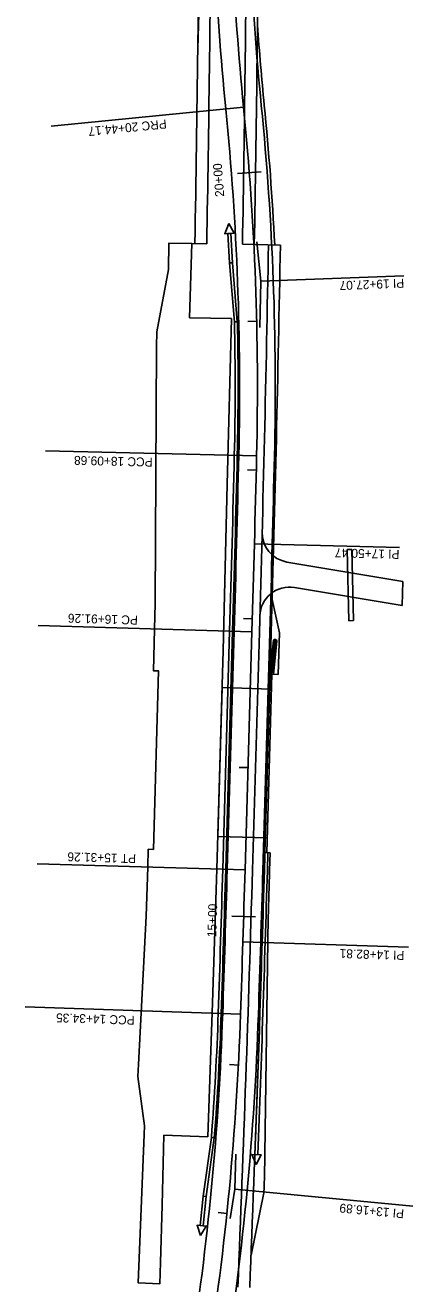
# Model space of a CAD drawing. Extents: x 1445610 to 1446352, y 2042797 to 2056486.
# Drawn here: x 1445983 to 1446244, y 2043758 to 2044604 of the extents above; entities that cross this region are included whole.
import ezdxf

# ---------------------------------------------------------------- set-up
doc = ezdxf.new("R2010")
doc.units = 0
for name, color, linetype in [('20', 7, 'Continuous'), ('Default', 7, 'Continuous'), ('Level 43', 7, 'Continuous'), ('MOT_Barrier Wall', 7, 'Continuous'), ('MOT_TIAB', 7, 'Continuous'), ('R_Bridge', 7, 'Continuous'), ('R_Horz Alg', 7, 'Continuous'), ('R_Horz Alg Annot', 7, 'Continuous'), ('R_Horz Alg Stationing', 7, 'Continuous'), ('R_Impact Attenuator', 7, 'Continuous'), ('R_Proposed Road', 7, 'Continuous'), ('R_Shld', 7, 'Continuous')]:
    doc.layers.add(name, color=color, linetype=linetype)

msp = doc.modelspace()

# ---------------------------------------------------------------- linework, layer by layer
at = {"layer": '20'}
for points in [[(1446099.19, 2044587.77), (1446099.81, 2044645.31), (1446100.22, 2044692.73), (1446100.65, 2044743.22), (1446101.46, 2044815.39), (1446102.41, 2044882.46), (1446103.41, 2044940.88), (1446106.1, 2045068.66), (1446107.43, 2045122.08), (1446109.28, 2045188.98), (1446109.28, 2045188.98), (1446109.52, 2045197.16), (1446117.13, 2045296.98), (1446119.67, 2045296.9), (1446109.26, 2044914.17), (1446105.78, 2044809.37), (1446102.6, 2044702.27), (1446099.67, 2044603.66)], [(1446106.06, 2043856.72), (1446076.44, 2043857.82), (1446075.37, 2043810.87), (1446074.2, 2043772.3), (1446073.76, 2043757.95), (1446059.18, 2043758.55), (1446063.09, 2043858.31), (1446063.3, 2043864.15), (1446058.99, 2043897.27), (1446059.27, 2043905.25), (1446064.53, 2044004.95), (1446065.52, 2044038.02), (1446065.87, 2044050.02), (1446069.37, 2044049.92), (1446072.86, 2044169.87), (1446069.36, 2044169.97), (1446070.17, 2044197.96), (1446070.66, 2044215.07), (1446071.41, 2044387.78), (1446071.61, 2044397.76), (1446079.43, 2044439.54), (1446079.75, 2044457.36), (1446095.2, 2044457.08), (1446093.66, 2044407.15), (1446121.8, 2044406.59), (1446119.04, 2044295.1), (1446116.28, 2044183.61), (1446112, 2044036.67), (1446109.03, 2043946.7)]]:
    msp.add_lwpolyline(points, close=True, dxfattribs=at)
at = {"layer": 'Default'}
msp.add_line((1446112.64, 2044058.66), (1446115.55, 2044158.62), dxfattribs=at)
at = {"layer": 'Level 43'}
for p, q in [((1446199.73, 2044251.32), (1446202.73, 2044251.39)), ((1446200.89, 2044203.54), (1446199.73, 2044251.32)), ((1446203.89, 2044203.61), (1446202.73, 2044251.39)), ((1446200.89, 2044203.54), (1446203.89, 2044203.61))]:
    msp.add_line(p, q, dxfattribs=at)
at = {"layer": 'MOT_Barrier Wall'}
for p, q in [((1446119.49, 2044463.76), (1446121.49, 2044463.87)), ((1446120.47, 2044443.95), (1446119.49, 2044463.77)), ((1446122.47, 2044444.05), (1446121.49, 2044463.87)), ((1446122.47, 2044444.05), (1446120.47, 2044443.95)), ((1446123.82, 2044404.26), (1446120.47, 2044443.95)), ((1446125.81, 2044404.43), (1446122.47, 2044444.05)), ((1446123.81, 2044404.39), (1446125.81, 2044404.43)), ((1446116, 2044036.55), (1446120.65, 2044196.49)), ((1446118, 2044036.5), (1446122.65, 2044196.43)), ((1446143.99, 2044035.74), (1446144.34, 2044047.73)), ((1446144.34, 2044047.73), (1446146.33, 2044047.68)), ((1446145.99, 2044035.68), (1446146.33, 2044047.68)), ((1446108.36, 2043856.32), (1446102.88, 2043816.94)), ((1446110.34, 2043856.04), (1446104.86, 2043816.67)), ((1446108.34, 2043856.2), (1446110.34, 2043856.04)), ((1446102.87, 2043816.87), (1446100.82, 2043797.14)), ((1446104.86, 2043816.67), (1446102.8, 2043796.93)), ((1446102.87, 2043816.87), (1446104.86, 2043816.67)), ((1446100.82, 2043797.14), (1446102.8, 2043796.93))]:
    msp.add_line(p, q, dxfattribs=at)
for centre, radius, start, end in [((1444229.47, 2044360.11), 1894.86, 358.62905, 1.33877), ((1444229.47, 2044360.11), 1896.86, 358.62905, 1.33877), ((1423202.54, 2044863.34), 22927.81, 358.333333, 358.629047), ((1423202.54, 2044863.34), 22929.81, 358.333333, 358.629047), ((1423197.89, 2044703.4), 22927.81, 358.091319, 358.333333), ((1423197.89, 2044703.4), 22929.81, 358.091319, 358.333333), ((1423197.89, 2044703.4), 22955.81, 357.856563, 358.333333), ((1423197.89, 2044703.4), 22957.81, 357.856563, 358.333333), ((1444219.17, 2044002.87), 1894.86, 355.56067, 358.09132), ((1444219.17, 2044002.87), 1896.86, 355.56067, 358.09132)]:
    msp.add_arc(centre, radius, start, end, dxfattribs=at)
at = {"layer": 'MOT_TIAB'}
for points in [[(1446120.12, 2044470.48), (1446123.62, 2044463.98), (1446117.36, 2044463.64)], [(1446138.39, 2043838.12), (1446135.5, 2043844.91), (1446141.77, 2043844.67)], [(1446101.12, 2043790.39), (1446098.69, 2043797.36), (1446104.93, 2043796.71)]]:
    msp.add_lwpolyline(points, close=True, dxfattribs=at)
at = {"layer": 'R_Bridge'}
for p, q in [((1446144.34, 2044047.73), (1446147.83, 2044167.68)), ((1446145.59, 2044047.7), (1446149.08, 2044167.65)), ((1446147.83, 2044167.68), (1446149.08, 2044167.65)), ((1446148.78, 2044157.65), (1446115.55, 2044158.62)), ((1446144.34, 2044047.73), (1446145.59, 2044047.7))]:
    msp.add_line(p, q, dxfattribs=at)
msp.add_lwpolyline([(1446112.64, 2044058.66), (1446145.88, 2044057.69)], dxfattribs=at)
at = {"layer": 'R_Horz Alg'}
msp.add_line((1446130.99, 2044036.12), (1446135.65, 2044196.05), dxfattribs=at)
for centre, radius, start, end in [((1448030.54, 2044737.1), 1909.86, 179.41289, 185.66397), ((1444229.47, 2044360.11), 1909.86, 358.62905, 5.66397), ((1423202.54, 2044863.34), 22942.81, 358.333333, 358.629047), ((1423197.89, 2044703.4), 22942.81, 358.091319, 358.333333), ((1444219.17, 2044002.87), 1909.86, 351.0345, 358.09132)]:
    msp.add_arc(centre, radius, start, end, dxfattribs=at)
at = {"layer": 'R_Horz Alg Annot'}
for p, q in [((1446138.98, 2044458.17), (1446141.59, 2044431.78)), ((1446141.59, 2044431.78), (1446237.72, 2044435.39)), ((1446141.59, 2044431.78), (1446140.85, 2044400.7)), ((1446234.84, 2044252.65), (1446137.37, 2044255.23)), ((1446240.93, 2043984.21), (1446129.58, 2043987.68)), ((1446124.05, 2043821.56), (1446124.83, 2043845.05)), ((1446124.05, 2043821.56), (1446120.93, 2043801.82)), ((1446243.84, 2043810.16), (1446124.05, 2043821.56))]:
    msp.add_line(p, q, dxfattribs=at)
for points in [[(1446130.01, 2044548.61), (1446000.64, 2044535.78)], [(1446138.78, 2044314.42), (1445996.69, 2044317.82)], [(1446135.65, 2044196.05), (1445991.86, 2044200.23)], [(1446130.99, 2044036.12), (1445991.27, 2044040.18)], [(1446127.97, 2043939.26), (1445983.12, 2043944.08)]]:
    msp.add_lwpolyline(points, dxfattribs=at)
at = {"layer": 'R_Horz Alg Stationing'}
for points in [[(1446125.88, 2044504), (1446141.83, 2044505.21)], [(1446132.81, 2044404.6), (1446138.81, 2044404.74)], [(1446132.55, 2044304.89), (1446138.55, 2044304.75)], [(1446129.9, 2044204.95), (1446135.9, 2044204.78)], [(1446126.99, 2044105), (1446132.99, 2044104.82)], [(1446122.07, 2044005.11), (1446138.06, 2044004.62)], [(1446120.52, 2043905.24), (1446126.52, 2043904.93)], [(1446112.81, 2043805.86), (1446118.78, 2043805.24)]]:
    msp.add_lwpolyline(points, dxfattribs=at)
at = {"layer": 'R_Impact Attenuator'}
for p, q in [((1446147.96, 2044167.8), (1446150.04, 2044190.04)), ((1446150.2, 2044167.59), (1446152.28, 2044189.83)), ((1446151.13, 2044190.94), (1446151.38, 2044190.92))]:
    msp.add_line(p, q, dxfattribs=at)
for centre in [(1446150.54, 2044189.37), (1446151.66, 2044189.27), (1446149.81, 2044181.53), (1446149.91, 2044182.65), (1446150.02, 2044183.77), (1446150.12, 2044184.89), (1446150.23, 2044186.01), (1446150.33, 2044187.13), (1446150.44, 2044188.25), (1446150.93, 2044181.43), (1446151.03, 2044182.55), (1446151.14, 2044183.67), (1446151.24, 2044184.79), (1446151.35, 2044185.91), (1446151.45, 2044187.03), (1446151.56, 2044188.15), (1446148.97, 2044172.57), (1446149.08, 2044173.69), (1446149.18, 2044174.81), (1446149.29, 2044175.93), (1446149.39, 2044177.05), (1446149.5, 2044178.17), (1446149.6, 2044179.29), (1446149.7, 2044180.41), (1446150.09, 2044172.47), (1446150.2, 2044173.59), (1446150.3, 2044174.71), (1446150.41, 2044175.83), (1446150.51, 2044176.95), (1446150.62, 2044178.07), (1446150.72, 2044179.19), (1446150.82, 2044180.31), (1446148.66, 2044169.21), (1446148.66, 2044169.21), (1446148.76, 2044170.33), (1446148.87, 2044171.45), (1446149.78, 2044169.11), (1446149.78, 2044169.11), (1446149.88, 2044170.23), (1446149.99, 2044171.35)]:
    msp.add_circle(centre, 0.563, dxfattribs=at)
for centre, start, end in [((1446151.04, 2044189.94), 84.65511, 174.65511), ((1446151.28, 2044189.92), 354.65511, 84.65511)]:
    msp.add_arc(centre, 1, start, end, dxfattribs=at)
at = {"layer": 'R_Proposed Road'}
for p, q in [((1446095.2, 2044457.08), (1446105.25, 2044456.9)), ((1446129.24, 2044456.48), (1446154.74, 2044456.02)), ((1446237.12, 2044229.88), (1446159.18, 2044242.99)), ((1446236.66, 2044213.73), (1446164.27, 2044225.91)), ((1446236.66, 2044213.73), (1446237.12, 2044229.88)), ((1446119, 2044036.47), (1446123.65, 2044196.4)), ((1446135.99, 2044035.97), (1446140.64, 2044195.9)), ((1446142.99, 2044035.77), (1446147.64, 2044195.7)), ((1446147.83, 2044167.68), (1446148.64, 2044195.67)), ((1446143.99, 2044035.74), (1446144.28, 2044045.74))]:
    msp.add_line(p, q, dxfattribs=at)
for centre, radius, start, end in [((1448030.54, 2044737.1), 1921.86, 179.41289, 185.66397), ((1448030.54, 2044737.1), 1897.86, 179.41289, 185.66397), ((1423202.54, 2044863.34), 22906.31, 358.983333, 359.573112), ((1423202.54, 2044863.34), 22930.31, 358.983333, 359.573112), ((1423202.54, 2044863.34), 22938.31, 358.983333, 359.573112), ((1448030.54, 2044737.1), 1895.86, 184.03516, 185.66397), ((1423202.54, 2044863.34), 22898.31, 358.983333, 359.310464), ((1444229.47, 2044360.11), 1897.86, 358.62905, 5.66397), ((1444229.47, 2044360.11), 1921.86, 358.62905, 5.66397), ((1444229.47, 2044360.11), 1923.86, 2.85957, 5.66397), ((1423202.54, 2044863.34), 22947.81, 358.333333, 358.983333), ((1423202.54, 2044863.34), 22955.81, 358.333333, 358.983333), ((1423202.54, 2044863.34), 22930.81, 358.333333, 358.629047), ((1423202.54, 2044863.34), 22954.81, 358.333333, 358.629047), ((1446162.5, 2044262.72), 20, 178.50152, 260.44833), ((1446160.95, 2044206.19), 20, 80.44833, 178.36045), ((1423197.89, 2044703.4), 22930.81, 358.091319, 358.333333), ((1423197.89, 2044703.4), 22947.81, 357.633333, 358.333333), ((1423197.89, 2044703.4), 22955.81, 357.633333, 358.333333), ((1423197.89, 2044703.4), 22954.81, 358.091319, 358.333333), ((1444219.17, 2044002.87), 1897.86, 351.0345, 358.09132), ((1444219.17, 2044002.87), 1921.86, 351.0345, 358.09132)]:
    msp.add_arc(centre, radius, start, end, dxfattribs=at)
at = {"layer": 'R_Shld'}
for p, q in [((1446154.14, 2044195.51), (1446149.27, 2044217.7)), ((1446154.14, 2044195.51), (1446153.32, 2044167.52)), ((1446153.32, 2044167.52), (1446149.08, 2044167.65)), ((1446147.83, 2044047.63), (1446145.59, 2044047.7)), ((1446147.49, 2044035.64), (1446147.83, 2044047.63)), ((1446144.05, 2043829.1), (1446146.56, 2044004.45)), ((1446135.01, 2043777.32), (1446143.66, 2043819.09))]:
    msp.add_line(p, q, dxfattribs=at)
for centre, radius, start, end in [((1424582.45, 2044662.17), 21574.13, 358.252958, 358.335833), ((1423197.89, 2044703.4), 22962.81, 357.792958, 357.817958)]:
    msp.add_arc(centre, radius, start, end, dxfattribs=at)

# ---------------------------------------------------------------- texts
at = {"layer": 'R_Horz Alg Annot'}
for s, rotation, p in [('PRC 20+44.17', 185.66397, (1446077.96, 2044540.43)), ('PI 19+27.07', 182.14895, (1446237.91, 2044433.34)), ('PCC 18+09.68', 178.62905, (1446068.92, 2044313.07)), ('PI 17+50.47', 178.48659, (1446234.93, 2044251.05)), ('PC 16+91.26', 178.33333, (1446059, 2044206.9)), ('PT 15+31.26', 178.33333, (1446057.79, 2044046.61)), ('PI 14+82.81', 178.20316, (1446238.24, 2043981.55)), ('PCC 14+34.35', 178.09132, (1446056.86, 2043938.01)), ('PI 13+16.89', 174.72804, (1446238.15, 2043807.93))]:
    msp.add_text(s, height=6, rotation=rotation, dxfattribs=at).set_placement(p)
at = {"layer": 'R_Horz Alg Stationing'}
for s, rotation, p in [('20+00', 94.33877, (1446117.02, 2044488.64)), ('15+00', 88.25526, (1446111.62, 2043990.78))]:
    msp.add_text(s, height=6, rotation=rotation, dxfattribs=at).set_placement(p)

doc.saveas('drawing.dxf')
